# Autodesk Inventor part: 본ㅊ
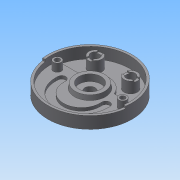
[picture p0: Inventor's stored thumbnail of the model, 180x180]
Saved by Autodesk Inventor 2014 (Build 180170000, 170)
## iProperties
Created: 2015-06
Part Number: 본ㅊ
Material: Generic
Document SubType Name: Modeling
Designer: Administrator
Density: 1 g/cm^3
Appearance: Default
Author: Administrator
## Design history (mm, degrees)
sketch "스케치1"
  geometry: C1 r 95 at (0, 0); 1 further point
  constraints: 1 centre point, 1 coincident
  dimensions: "d0" = 190 diameter of C1
extrude "돌출1" new body sketch "스케치1" distance "d1" = 32; taper "d2" = 0 deg
sketch "스케치2"
  geometry: C1 r 95 at (0, 0) reference; C2 r 90 at (0, 0)
  constraints: 1 centre point, 1 coincident
  dimensions: "d7" = 180 diameter of C2
extrude "돌출2" cut sketch "스케치2" distance "d8" = 18; taper "d9" = 0 deg
sketch "스케치4"
  geometry: L1 (-88.566, 16)-(-38.833, 16); L2 (38.833, 16)-(88.566, 16); A1 r 90 centre (0, 0) between (88.566, 16) and (-88.566, 16) reference; A2 r 42 centre (0, 0) between (-38.833, 16) and (38.833, 16); 1 further point
  constraints: 4 end point, 4 point on circle, 2 horizontal, 1 centre point, 1 coincident, 1 vertical alignment
  dimensions: "d12" = 84 diameter of A2; "d14" = 16 distance of A1.centre point (0, 16); "d15" = 38.83298 distance of point (0, 16) L1.end; "d16" = 38.83298 distance of L2.start point (0, 16)
extrude "돌출4" cut sketch "스케치4" distance "d19" = 7; taper "d20" = 0 deg
sketch "스케치5"
  geometry: L1 (0, 0)-(95, 0); L2 (0, 0)-(-95, 0); L3 (0, 0)-(-94.075, -13.221); L4 (0, 0)-(94.075, -13.221); A1 r 95 centre (0, 0) between (95, 0) and (-95, 0) reference
  constraints: 8 end point, 4 point on circle, 1 collinear, 1 horizontal
  dimensions: "d21" = 8 deg angle of L3 L2; "d22" = 8 deg angle of L4 L1
extrude "돌출5" cut sketch "스케치5" distance "d23" = 5; taper "d24" = 0 deg
sketch "스케치6"
  geometry: C1 r 15 at (-40, 52); C2 r 15 at (40, 52); A1 r 90 centre (0, 0) between (88.566, 16) and (-88.566, 16) reference
  constraints: 2 centre point, 1 equal radius, 1 horizontal alignment
  dimensions: "d25" = 52 vertical distance of A1.centre C2.centre; "d26" = 30 diameter of C1; "d27" = 40 horizontal distance of A1.centre C1.centre; "d28" = 40 horizontal distance of C2.centre A1.centre
extrude "돌출6" join sketch "스케치6" distance "d29" = 25; taper "d30" = 0 deg
hole "구멍1" diameter "d33" = 20; stored, may be unused: countersink angle "d37" = 90 deg, drill point angle "d39" = 118 deg; dims "d31" = 10, "d32" = 10, "d34" = 6, "d35" = 4, "d36" = 2, "d38" = 8
hole "구멍2" diameter "d42" = 20; stored, may be unused: countersink angle "d46" = 90 deg, drill point angle "d48" = 118 deg; dims "d40" = 10, "d41" = 10, "d43" = 6, "d44" = 4, "d45" = 2, "d47" = 8
sketch "스케치7"
  geometry: L1 (-6, 20.367)-(6, 20.367); L2 (6, 20.367)-(6, -20.367); L3 (6, -20.367)-(-6, -20.367); L4 (-6, -20.367)-(-6, 20.367); L5 (-6, 20.367)-(6, -20.367); L6 (6, 20.367)-(-6, -20.367); L7 (58.462, 6)-(101.538, 6); L8 (101.538, 6)-(101.538, -6); L9 (101.538, -6)-(58.462, -6); L10 (58.462, -6)-(58.462, 6); L11 (58.462, 6)-(101.538, -6); L12 (101.538, 6)-(58.462, -6); C1 r 15 at (0, 0) reference; C2 r 15 at (80, 0) reference; 1 further point
  constraints: 24 end point, 4 midpoint, 4 parallel, 2 horizontal, 2 perpendicular
  dimensions: "d49" = 12 distance of L1.start L1.end; "d50" = 12 distance of L7.end L8.end; "d51" = 43.07513 distance between parallel lines of L8 L10; "d52" = 40.7331 distance between parallel lines of L3 L1
extrude "돌출7" cut sketch "스케치7" distance "d53" = 3; taper "d54" = 0 deg
sketch "스케치8"
  geometry: C1 r 35 at (0, 0); A1 r 90 centre (0, 0) between (-88.566, 16) and (88.566, 16) reference
  constraints: 1 centre point, 1 coincident
  dimensions: "d55" = 70 diameter of C1
extrude "돌출8" join sketch "스케치8" distance "d56" = 10; taper "d57" = -10 deg
sketch "스케치9"
  geometry: C1 r 95 at (0, 0) reference; C2 r 26 at (0, 0)
  constraints: 1 centre point, 1 coincident
  dimensions: "d58" = 52 diameter of C2
extrude "돌출9" join sketch "스케치9" distance "d59" = 12; taper "d60" = -15 deg
hole "구멍3" diameter "d63" = 23; stored, may be unused: countersink angle "d67" = 90 deg, drill point angle "d69" = 118 deg; dims "d61" = 10, "d62" = 10, "d64" = 6, "d65" = 50, "d66" = 15, "d68" = 8
sketch "스케치10"
  geometry: L1 (-59, -19)-(-59, -14); L2 (-41, -19)-(-41, -14); L3 (41, -19)-(41, -14); L4 (59, -19)-(59, -14); L5 (41, -14)-(59, -14); L6 (-41, -14)-(-59, -14); C1 r 35 at (0, 0) reference; A1 r 41 centre (0, -19) between (-41, -19) and (41, -19); A2 r 59 centre (0, -19) between (-59, -19) and (59, -19); 5 further points
  constraints: 12 end point, 4 perpendicular, 4 point on circle, 4 tangent, 2 centre point, 2 coincident, 2 horizontal alignment, 2 midpoint, 2 vertical alignment, 1 parallel, 4 other
  dimensions: "d73" = 59 radius of A2; "d74" = 41 radius of A1; "d76" = 19 distance of C1.centre A2.centre; "d77" = 14 distance of C1.centre point (0, -14); "d78" = 14 distance from line of C1.centre L6; "d79" = 0 distance between parallel lines of L6 L5; "d80" = 29.56636 distance from line of point (88.566, 16) L4
extrude "돌출10" cut sketch "스케치10" distance "d81" = 7; taper "d82" = 0 deg
sketch "스케치11"
  geometry: C1 r 35 at (0, 0) reference; C2 r 9 at (-74, 0); C3 r 9 at (74, 0); A1 r 42 centre (0, 0) between (38.833, 16) and (-38.833, 16) reference; A2 r 15 centre (-40, 52) between (-46, 65.748) and (-46, 38.252) reference; A3 r 15 centre (40, 52) between (53.748, 58) and (26.252, 58) reference
  constraints: 2 centre point, 1 equal radius
  dimensions: "d83" = 18 diameter of C2; "d84" = 52 vertical distance of C2.centre A2.centre; "d85" = 52 vertical distance of C3.centre A3.centre; "d86" = 74 distance of A1.centre C2.centre; "d87" = 74 distance of C3.centre C1.centre
extrude "돌출11" join sketch "스케치11" distance "d88" = 18; taper "d89" = 0 deg
sketch "스케치12"
  geometry: C1 r 9 at (-74, 0) reference; C2 r 9 at (74, 0) reference; 2 further points
  constraints: 2 coincident
hole "구멍4" sketch "스케치12" at (-74, 0), (74, 0) diameter "d90" = 11; stored, may be unused: countersink angle "d94" = 90 deg, drill point angle "d96" = 118 deg; dims "d91" = 6, "d92" = 18, "d93" = 11, "d95" = 8
sketch "스케치13"
  geometry: C1 r 95 at (0, 0) reference; C2 r 68 at (0, 0)
  constraints: 1 centre point, 1 coincident, 1 other
  dimensions: "d97" = 136 diameter of C2
feature "엠보싱1" sketch "스케치13" dims "d98" = 0.5, "d99" = 0
node "솔리드1"
other parameters: "d71" = 59, "d72" = 41
